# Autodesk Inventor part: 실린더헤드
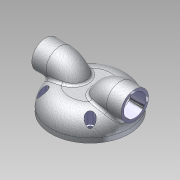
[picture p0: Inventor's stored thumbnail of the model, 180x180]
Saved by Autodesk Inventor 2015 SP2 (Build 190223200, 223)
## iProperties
Manager: KYOUNG IL JANG
Company: 한국ATC센터
Created: 2012-10
Part Number: 실린더헤드
Document SubType Name: Modeling
Density: 1 g/cm^3
Checked By: KYOUNG IL JANG
Vendor: CBT Solutions
Designer: KYOUNG IL JANG
Material: 일반
Appearance: _시험_알루미늄 표면거칠기
Author: KYOUNG IL JANG
## Parameters: d0 = 85 mm, d1 = 25 mm, d2 = 0, d5 = 5 mm, d6 = 0, d7 = 16 mm, d8 = 6 mm, d11 = 105 deg, d13 = 3 mm, d14 = 0, d15 = 0, d16 = 15 mm, d17 = 15 mm, d18 = 5 mm, d19 = 90 deg, d20 = 3 mm, d22 = 72.5 mm, d23 = 5.5 mm, d24 = 9.5 mm, d25 = 5 mm, d26 = 0, d27 = 5 mm, d28 = 0, d30 = 360 deg, d33 = 1 mm, d34 = 2 mm, d35 = 45 deg, d36 = 15.5 mm, d37 = 45 deg, d38 = 0, d39 = 0
